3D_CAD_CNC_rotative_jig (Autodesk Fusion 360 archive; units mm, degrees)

design "CNC jig F1-Version02" references "f1_blank", "CNC table work"
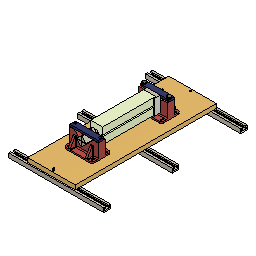
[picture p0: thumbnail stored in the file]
description: Part Number
part number: 94180A353_Brass Tapered Heat-Set Inserts for Plastic
part number: 94459A180_Heat-Set Inserts for Plastic
part number: 96016A241_Plastic-Head Thumb Screws
part number: 92005A218_Steel Pan Head Phillips Screw
part number: 92770A117_Black-Oxide Steel Machined Neck T-Slot Bolt
component_insert "Component Insert1"
position "Position1"
sketch "Sketch2" plane through (0, 0, 0) normal (0, 0, 1) x axis (-1, 0, 0)
  line L1 (0, -35.5) -> (6, -35.5)
  line L2 (0, -65) -> (0, -35.5)
  line L3 (50, -65) -> (0, -65)
  line L4 (50, 0) -> (50, -65)
  line L5 (0, 0) -> (50, 0)
  line L6 (0, -29.5) -> (0, 0)
  line L7 (6, -29.5) -> (0, -29.5)
  line L8 (6, -35.5) -> (6, -29.5)
  line L9 (0, 0) -> (50, -65)
  line L10 (50, 0) -> (0, -65)
  line L11 (25, -53.7132) -> (3.7868, -32.5)
  line L12 (46.2132, -32.5) -> (25, -53.7132)
  line L13 (25, -11.2868) -> (46.2132, -32.5)
  line L14 (3.7868, -32.5) -> (25, -11.2868)
  line L15 (46.2132, -32.5) -> (3.7868, -32.5)
  line L16 (25, -11.2868) -> (25, -53.7132)
  line L17 (25, -4.2157) -> (53.2843, -32.5)
  line L18 (-3.2843, -32.5) -> (25, -4.2157)
  line L19 (25, -60.7843) -> (-3.2843, -32.5)
  line L20 (53.2843, -32.5) -> (25, -60.7843)
  circle C1 centre (29, -32.5) radius 9
  circle C2 centre (29, -32.5) radius 10.5
  point P11 (25, -32.5)
  point P16 (25, -32.5)
  point P14 (46.2132, -32.5)
  point P15 (25, -11.2868)
  point P13 (25, -53.7132)
  midpoint L9 P11
  perpendicular L11 L12
  parallel L11 L13
  parallel L12 L14
  coincident L15 P16
  coincident L16 P16
  coincident P11 P16
  vertical L16
  concentric C1 C2
  dimension "d31" distance P14 P15 = 30
  dimension "d32" distance P13 P14 = 30
  dimension "d36" diameter C2 = 21
  dimension "d42" = 5
sketch "Sketch3" plane through (0, 0, -223) normal (0, 0, -1) x axis (1, 0, 0)
  line L1 (-6, -35.5) -> (0, -35.5)
  line L2 (-6, -29.5) -> (-6, -35.5)
  line L3 (0, -29.5) -> (-6, -29.5)
  line L4 (0, 0) -> (0, -29.5)
  line L5 (-50, 0) -> (0, 0)
  line L6 (-50, -65) -> (-50, 0)
  line L7 (0, -65) -> (-50, -65)
  line L8 (0, -35.5) -> (0, -65)
  line L9 (-50, -32.5) -> (0, -32.5)
  line L10 (-29, 0) -> (-29, -65)
  line L11 (5, 0) -> (-50, 0)
  line L12 (5, -65) -> (5, 0)
  line L13 (-50, -65) -> (5, -65)
  line L14 (-50, 0) -> (-50, -65)
  line L15 (-50, 0) -> (0, -65)
  line L16 (0, 0) -> (-50, -65)
  line L17 (-3.7868, -32.5) -> (-25, -53.7132)
  line L18 (-25, -11.2868) -> (-3.7868, -32.5)
  line L19 (-46.2132, -32.5) -> (-25, -11.2868)
  line L20 (-25, -53.7132) -> (-46.2132, -32.5)
  line L21 (-25, -11.2868) -> (-25, -53.7132)
  line L22 (-46.2132, -32.5) -> (-3.7868, -32.5)
  line L23 (0, -29.5) -> (0, -35.5)
  line L24 (-50, -65) -> (0, -65)
  circle C1 centre (-29, -32.5) radius 9
  point P13 (-50, -32.5)
  point P14 (-29, -65)
  point P15 (-29, 0)
  point P10 (-29, -32.5)
  point P19 (-29, -32.5)
  point P1 (0, 0)
  point P20 (0, 0)
  point P21 (-25, -32.5)
  point P26 (-25, -32.5)
  point P11 (-28.998, -32.6276)
  point P24 (-25, -11.2868)
  point P25 (-46.2132, -32.5)
  point P23 (-3.7868, -32.5)
  midpoint L6 P13
  perpendicular L6 L9
  coincident L7 P14
  coincident L5 P15
  perpendicular L5 L10
  horizontal L11
  vertical L12
  horizontal L13
  vertical L14
  coincident P10 P19
  coincident P1 P20
  midpoint L9 P21
  perpendicular L17 L18
  parallel L17 L19
  parallel L18 L20
  coincident L21 P26
  coincident L22 P26
  coincident P21 P26
  horizontal L22
  dimension "d5" distance L8 L12 = 5
  dimension "d8" distance P11 P21 = 4
  dimension "d9" distance P24 P25 = 30
  dimension "d10" distance P23 P24 = 30
extrude "Extrude1" new body sketch "Sketch3" profile of L1 L2 L3 L4 L8 L11 L13 L14 L17 L18 L19 L20 L23 along normal blind 15 bodies "front end block"
extrude "Extrude2" new body sketch "Sketch3" profile of L4 L8 L11 L12 L13 L23 along normal blind 15 bodies "front end block plate wirh slot"
extrude "Extrude3" new body sketch "Sketch3" profile of L1 L2 L3 L4 L8 L11 L12 L13 L23 against normal blind 10
extrude "Extrude4" sketch "Sketch3" profile of L17 L18 L19 L20 blind 50 bodies "front end square axis"
sketch "Sketch4" plane through (0, 0, -238) normal (0, 0, -1) x axis (-1, 0, 0)
  line L1 (0, 0) -> (0, 65)
  line L2 (50, 0) -> (0, 0)
  line L3 (50, 65) -> (50, 0)
  line L4 (0, 65) -> (50, 65)
  line L5 (46.2132, 32.5) -> (25, 11.2868)
  line L6 (25, 53.7132) -> (46.2132, 32.5)
  line L7 (3.7868, 32.5) -> (25, 53.7132)
  line L8 (25, 11.2868) -> (3.7868, 32.5)
  line L9 (25, -13.7132) -> (25, 11.2868)
  line L10 (85, -13.7132) -> (25, -13.7132)
  line L11 (65, 51.2868) -> (25, 11.2868)
  line L12 (85, 51.2868) -> (65, 51.2868)
  line L13 (85, -13.7132) -> (85, 51.2868)
  line L14 (-5, 0) -> (50, 0)
  line L15 (25, 71.245) -> (25, 11.2868)
  line L16 (25, 51.2868) -> (65, 51.2868)
  line L17 (-35, -13.7132) -> (-35, 51.2868)
  line L18 (-35, 51.2868) -> (-15, 51.2868)
  line L19 (-15, 51.2868) -> (25, 11.2868)
  line L20 (-35, -13.7132) -> (25, -13.7132)
  line L21 (26.5, 11.1475) -> (26.5, 12.7868)
  line L22 (25, 9.6475) -> (25, 9.6475)
  line L23 (23.5, 11.1475) -> (23.5, 12.7868)
  arc A1 centre (25, 11.1475) radius 1.5 clockwise from (26.5, 11.1475) to (25, 9.6475)
  arc A2 centre (25, 11.1475) radius 1.5 clockwise from (25, 9.6475) to (23.5, 11.1475)
  point P6 (25, 11.2868)
  point P10 (25, 11.2868)
  point P17 (25, 11.2868)
  point P19 (25, 51.2868)
  point P23 (25, 11.2868)
  point P11 (25, -13.7132)
  point P24 (25, -13.7132)
  point P12 (65, 51.2868)
  point P22 (-15, 51.2868)
  point P13 (85, 51.2868)
  point P20 (-35, 51.2868)
  point P14 (85, -13.7132)
  point P21 (-35, -13.7132)
  point P25 (26.5, 12.7868)
  point P26 (25, 9.6475)
  point P29 (23.5, 12.7868)
  point P32 (25, 9.6475)
  point P27 (26.5, 11.1475)
  point P30 (23.5, 11.1475)
  coincident P6 P10
  perpendicular L2 L9
  perpendicular L9 L10
  perpendicular L6 L11
  parallel L10 L12
  perpendicular L10 L13
  coincident P6 P17
  perpendicular L4 L15
  coincident L15 P19
  perpendicular L15 L16
  symmetric P10 L9 P23
  symmetric P11 L9 P24
  symmetric L9 P12 P22
  symmetric L9 P13 P20
  symmetric L9 P14 P21
  coincident L11 P25
  vertical L21
  coincident L9 P26
  tangent L21 A1
  symmetric L9 P25 P29
  symmetric L9 P26 P32
  symmetric L9 P27 P30
  symmetric L9 A1 A2
  dimension "d20" distance P10 P11 = 25
  dimension "d26" distance P11 P14 = 60
  dimension "d27" distance P13 P14 = 65
  dimension "d28" angle L11 L14 = 45
  dimension "d62" distance L9 L21 = 1.5
  dimension "d64" radius A1 = 1.5
extrude "Extrude5" new body sketch "Sketch4" profile of L1 L2 L3 L5 L8 L10 L11 L12 L13 L14 L17 L18 L19 L20 L21 A1 L23 A2 along normal blind 30
extrude "Extrude6" new body sketch "Sketch2" profile of C1 against normal blind 50 bodies "rear end axis"
chamfer "Chamfer1" distance 3
extrude "Extrude7" add sketch "Sketch2" profile of C1 L12 L13 C2 along normal blind 30
extrude "Extrude8" sketch "Sketch2" profile of C1 L11 L12 L13 L14 C2 blind 39
hole "Hole1" HoleDepth 12 HoleDiameter 6 TipAngle 118 RefDim1 15 RefDim2 8
hole "Hole2" HoleDepth 12 HoleDiameter 6 TipAngle 118 RefDim1 8 RefDim2 15
copy_paste_bodies "CopyPasteBodies1"
move "Move1"
move "Move2"
extrude "Extrude9" sketch "Sketch2" profile of C1 L11 L12 L13 L14 C2 L17 L18 L19 L20 blind 9
ground "Ground1"
ground "Ground2"
move "Move3"
move "Move4"
sketch "Sketch5" plane through (0, 51.2868, 0) normal (0, 1, 0) x axis (0, 0, -1)
  line L1 (238, -35) -> (238, -15)
  line L2 (268, -35) -> (238, -35)
  line L3 (268, -15) -> (268, -35)
  line L4 (238, -15) -> (268, -15)
  line L5 (238, 65) -> (238, 85)
  line L6 (268, 65) -> (238, 65)
  line L7 (268, 85) -> (268, 65)
  line L8 (238, 85) -> (268, 85)
  line L9 (253, -27) -> (253, 77)
  line L10 (245.5, 85) -> (260.5, 85)
  line L11 (245.5, -35) -> (245.5, 85)
  line L12 (260.5, -35) -> (245.5, -35)
  line L13 (260.5, 85) -> (260.5, -35)
  line L14 (245.5, -35) -> (260.5, 85)
  line L15 (245.5, 73.75) -> (253, 73.75)
  line L16 (245.5, 80.25) -> (253, 80.25)
  line L17 (245.5, -23.75) -> (253, -23.75)
  line L18 (245.5, -30.25) -> (253, -30.25)
  circle C1 centre (253, -27) radius 3
  circle C2 centre (253, 77) radius 3
  circle C3 centre (253, 77) radius 3.25
  circle C4 centre (253, -27) radius 3.25
  point P7 (253, 77)
  point P14 (253, 77)
  point P2 (253, -27)
  point P15 (253, -27)
  point P20 (253, 73.75)
  point P21 (245.5, 73.75)
  point P22 (253, 80.25)
  point P23 (245.5, 80.25)
  point P24 (253, -23.75)
  point P25 (245.5, -23.75)
  point P26 (253, -30.25)
  point P27 (245.5, -30.25)
  point P16 (260.5, 85)
  point P19 (260.5, -35)
  point P17 (245.5, 85)
  concentric C2 C3
  concentric C1 C4
  coincident P7 P14
  coincident P2 P15
  horizontal L10
  vertical L11
  horizontal L12
  vertical L13
  midpoint L9 L14
  coincident C3 P20
  coincident L9 P20
  coincident L11 P21
  tangent C3 L15
  coincident C3 P22
  coincident L11 P23
  tangent C3 L16
  perpendicular L11 L16
  coincident L9 P24
  coincident C4 P24
  coincident L11 P25
  tangent C4 L17
  coincident C4 P26
  coincident L11 P27
  tangent C4 L18
  perpendicular L11 L18
  dimension "d56" diameter C3 = 6.5
  dimension "d57" diameter C4 = 6.5
  dimension "d58" distance P16 P19 = 120
  dimension "d59" distance P16 P17 = 15
extrude "Extrude10" new body sketch "Sketch5" profile of L2 L8 C3 C4 L10 L11 L12 L13 L15 L16 L17 L18 along normal blind 4 bodies "locking plate 1"
combine "Combine1"
component_insert "Component Insert2"
position "Position2"
position "Position3"
sketch "Sketch6" plane through (0, 0, 59) normal (0, 0, 1) x axis (1, 0, 0)
  line L1 (-23.5, 12.7868) -> (15, 51.2868)
  line L2 (-23.5, 11.1475) -> (-23.5, 12.7868)
  line L3 (-26.5, 12.7868) -> (-26.5, 11.1475)
  line L4 (-65, 51.2868) -> (-26.5, 12.7868)
  line L5 (-85, 51.2868) -> (-65, 51.2868)
  line L6 (-85, -13.7132) -> (-85, 51.2868)
  line L7 (35, -13.7132) -> (-85, -13.7132)
  line L8 (35, 51.2868) -> (35, -13.7132)
  line L9 (15, 51.2868) -> (35, 51.2868)
  line L10 (35, -13.7132) -> (35, 16.2868)
  line L11 (55, -13.7132) -> (35, -13.7132)
  line L12 (55, -11.7132) -> (55, -13.7132)
  line L13 (37, 16.2868) -> (35, 16.2868)
  line L14 (37, -11.7132) -> (37, 16.2868)
  line L15 (55, -11.7132) -> (37, -11.7132)
  arc A1 centre (-25, 11.1475) radius 1.5 clockwise from (-23.5, 11.1475) to (-26.5, 11.1475)
  point P13 (35, 16.2868)
  point P14 (35, -13.7132)
  point P15 (55, -13.7132)
  point P16 (55, -11.7132)
  point P17 (37, 16.2868)
  parallel L8 L10
  perpendicular L8 L11
  vertical L12
  perpendicular L10 L13
  perpendicular L13 L14
  perpendicular L12 L15
  dimension "d66" distance P13 P14 = 30
  dimension "d67" distance P14 P15 = 20
  dimension "d68" distance P15 P16 = 2
  dimension "d69" distance P13 P17 = 2
hole "Hole3" HoleDepth 2 HoleDiameter 3 TipAngle 118 RefDim1 7 RefDim2 10 CSDiameter 5 CSAngle 100
work_plane "WorkPlane1"
mirror "Mirror1"
mirror_component "MirrorComponent1"
sketch "Sketch7" plane through (0, 0, 69) normal (0, 0, 1) x axis (1, 0, 0)
  line L1 (-25, 11.2868) -> (-46.2132, 32.5)
  line L2 (-3.7868, 32.5) -> (-25, 11.2868)
  line L3 (-25, 53.7132) -> (-3.7868, 32.5)
  line L4 (-46.2132, 32.5) -> (-25, 53.7132)
  circle C1 centre (-25, 32.5) radius 10
  dimension "d102" diameter C1 = 20
extrude "Extrude11" add sketch "Sketch7" profile of C1 along normal blind 100
chamfer "Chamfer2" distance 2
offset_faces "OffsetFaces1" distance 10
combine "Combine2"
offset_faces "OffsetFaces2" distance -0.15
chamfer "Chamfer3" sketch "Sketch3" distance 2
chamfer "Chamfer4" sketch "Sketch3" distance 2
split "Split1" bodies "handle"
extrude "Extrude12" add of existing geometry blind 4
base_feature "Base Feature1"
move "Move1"
position "Position5"
copy_paste "CopyPaste1"
position "Position6"
position "Position7"
sketch "Sketch8" plane through (0, 0, -268) normal (0, 0, -1) x axis (-1, 0, 0)
  line L1 (-15, 51.2868) -> (23.5, 12.7868)
  line L2 (-35, 51.2868) -> (-15, 51.2868)
  line L3 (-35, -13.7132) -> (-35, 51.2868)
  line L4 (85, -13.7132) -> (-35, -13.7132)
  line L5 (85, 51.2868) -> (85, -13.7132)
  line L6 (65, 51.2868) -> (85, 51.2868)
  line L7 (26.5, 12.7868) -> (65, 51.2868)
  line L8 (26.5, 11.1475) -> (26.5, 12.7868)
  line L9 (23.5, 12.7868) -> (23.5, 11.1475)
  line L10 (30.5, 11.1475) -> (30.5, 12.7868)
  line L11 (19.5, 12.7868) -> (19.5, 11.1475)
  line L12 (85, -7.7132) -> (-35, -7.7132)
  arc A1 centre (25, 11.1475) radius 1.5 clockwise from (26.5, 11.1475) to (23.5, 11.1475)
  point P17 (-35, -7.7132)
  point P18 (85, -7.7132)
  coincident L3 P17
  coincident L5 P18
  perpendicular L5 L12
  dimension "d117" = -4
  dimension "d118" distance L4 L12 = 6
extrude "Extrude13" add sketch "Sketch8" profile of L3 L4 L5 L12 along normal blind 25
sketch "Sketch9" plane through (-85, 0, 0) normal (-1, 0, 0) x axis (0, 0, 1)
  line L1 (-238, 51.2868) -> (-238, -13.7132)
  line L2 (-268, 51.2868) -> (-238, 51.2868)
  line L3 (-268, -7.7132) -> (-268, 51.2868)
  line L4 (-293, -7.7132) -> (-268, -7.7132)
  line L5 (-293, -13.7132) -> (-293, -7.7132)
  line L6 (-238, -13.7132) -> (-293, -13.7132)
  line L7 (-293, -7.7132) -> (-268, -7.7132)
  line L8 (-293, -13.7132) -> (-293, -7.7132)
  line L9 (-293, -13.7132) -> (-238, -13.7132)
  line L10 (-238, -13.7132) -> (-238, 51.2868)
  line L11 (-268, -7.7132) -> (-268, 51.2868)
  line L12 (-268, 51.2868) -> (-238, 51.2868)
  line L13 (-293, -2.7132) -> (-293, -7.7132)
  line L14 (-273, 32.2868) -> (-268, 32.2868)
  line L15 (-293, -2.7132) -> (-273, 32.2868)
  point P9 (-293, -7.7132)
  point P14 (-293, -7.7132)
  point P16 (-268, 32.2868)
  point P15 (-293, -2.7132)
  point P17 (-273, 32.2868)
  coincident P9 P14
  perpendicular L7 L13
  coincident L3 P16
  perpendicular L3 L14
  dimension "d121" distance P14 P15 = 5
  dimension "d122" distance P16 P17 = 5
  dimension "d123" distance L7 L14 = 40
extrude "Extrude14" add sketch "Sketch9" profile of L3 L4 L7 L11 L13 L14 L15 blind -8 from offset -20
work_plane "WorkPlane2"
mirror "Mirror2" mirrorStitchTolerance 0.1
sketch "Sketch10" plane through (0, -7.7132, 0) normal (0, 1, 0) x axis (-1, 0, 0)
  line L1 (-15, -268) -> (-15, -293)
  line L2 (-35, -268) -> (-15, -268)
  line L3 (-35, -293) -> (-35, -268)
  line L4 (-15, -293) -> (-35, -293)
  line L5 (-7, -293) -> (-7, -268)
  line L6 (57, -293) -> (-7, -293)
  line L7 (57, -268) -> (57, -293)
  line L8 (-7, -268) -> (57, -268)
  line L9 (65, -293) -> (65, -268)
  line L10 (85, -293) -> (65, -293)
  line L11 (85, -268) -> (85, -293)
  line L12 (65, -268) -> (85, -268)
  line L13 (-15, -280.5) -> (-35, -280.5)
  line L14 (-25, -293) -> (-25, -268)
  line L15 (-27.6, -283.5) -> (-27.6, -277.5)
  line L16 (-22.4, -277.5) -> (-22.4, -283.5)
  line L17 (-25, -283.5) -> (-25, -277.5)
  line L18 (75, -293) -> (75, -268)
  line L19 (85, -280.5) -> (65, -280.5)
  line L20 (72.4, -283.5) -> (72.4, -277.5)
  line L21 (77.6, -277.5) -> (77.6, -283.5)
  line L22 (75, -283.5) -> (75, -277.5)
  arc A1 centre (-25, -283.5) radius 2.6 clockwise from (-22.4, -283.5) to (-27.6, -283.5)
  arc A2 centre (-25, -277.5) radius 2.6 clockwise from (-27.6, -277.5) to (-22.4, -277.5)
  arc A3 centre (75, -283.5) radius 2.6 clockwise from (77.6, -283.5) to (72.4, -283.5)
  arc A4 centre (75, -277.5) radius 2.6 clockwise from (72.4, -277.5) to (77.6, -277.5)
  point P14 (-35, -280.5)
  point P15 (-15, -280.5)
  point P16 (-25, -268)
  point P17 (-25, -293)
  point P24 (-25, -280.5)
  point P25 (75, -268)
  point P26 (75, -293)
  point P27 (65, -280.5)
  point P28 (85, -280.5)
  point P35 (75, -280.5)
  point P34 (75, -283.5)
  midpoint L3 P14
  midpoint L1 P15
  midpoint L2 P16
  midpoint L4 P17
  tangent L15 A1
  tangent A1 L16
  parallel L15 L16
  tangent L16 A2
  tangent L15 A2
  perpendicular L14 L17
  midpoint L13 P24
  midpoint L17 P24
  midpoint L12 P25
  midpoint L10 P26
  midpoint L9 P27
  midpoint L11 P28
  tangent L20 A3
  tangent A3 L21
  parallel L20 L21
  tangent L21 A4
  tangent L20 A4
  perpendicular L19 L22
  midpoint L19 P35
  midpoint L22 P35
  dimension "d130" diameter A1 = 5.2
  dimension "d131" diameter A3 = 5.2
  dimension "d132" distance L19 P34 = 3
extrude "Extrude15" cut sketch "Sketch10" profile of L15 A1 L16 A2 L20 A3 L21 A4 against normal blind 15
fillet "Fillet1" radius 10
fillet "Fillet2" radius 4
fillet "Fillet3" radius 2
work_plane "WorkPlane3"
mirror "Mirror3" mirrorStitchTolerance 0.1
mirror "Mirror4" mirrorStitchTolerance 0.1
fillet "Fillet4" radius 4
fillet "Fillet5" radius 10
offset_faces "OffsetFaces4" distance 6
combine "Combine3" bodies "front end block plate wirh slot"
combine "Combine4" bodies "front end square axis"
hole "Hole4" HoleDepth 10 HoleDiameter 5 TipAngle 118 RefDim1 15 RefDim2 8
hole "Hole5" HoleDepth 10 HoleDiameter 5 TipAngle 118 RefDim1 15 RefDim2 8
copy_paste "CopyPaste3"
position "Position11"
copy_paste "CopyPaste4"
offset_faces "OffsetFaces5" distance 2
sketch "Sketch11" plane through (0, 0, 39) normal (0, 0, 1) x axis (1, 0, 0)
  line L1 (-25, 60.7843) -> (3.2843, 32.5)
  line L2 (-53.2843, 32.5) -> (-25, 60.7843)
  line L3 (-25, 4.2157) -> (-53.2843, 32.5)
  line L4 (3.2843, 32.5) -> (-25, 4.2157)
  line L5 (-23.5858, 52.299) -> (-26.4142, 52.299)
  line L6 (-5.201, 33.9142) -> (-23.5858, 52.299)
  line L7 (-5.201, 31.0858) -> (-5.201, 33.9142)
  line L8 (-23.5858, 12.701) -> (-5.201, 31.0858)
  line L9 (-26.4142, 12.701) -> (-23.5858, 12.701)
  line L10 (-44.799, 31.0858) -> (-26.4142, 12.701)
  line L11 (-44.799, 33.9142) -> (-44.799, 31.0858)
  line L12 (-26.4142, 52.299) -> (-44.799, 33.9142)
  line L13 (0, 35.5) -> (-6, 35.5)
  line L14 (-6, 35.5) -> (-6, 29.5)
  line L15 (-6, 29.5) -> (0, 29.5)
  line L16 (-3, 35.5) -> (0.2843, 35.5)
  line L17 (-3, 29.5) -> (-3, 35.5)
  line L18 (0.2843, 29.5) -> (-3, 29.5)
  point P20 (0.2843, 35.5)
  point P21 (-3, 35.5)
  point P22 (-3, 29.5)
  point P23 (0.2843, 29.5)
  coincident L1 P20
  midpoint L13 P21
  parallel L13 L16
  midpoint L15 P22
  coincident L4 P23
  perpendicular L17 L18
extrude "Extrude16" cut sketch "Sketch11" profile of L1 L4 L13 L15 L16 L17 L18 against normal blind 15
mirror "Mirror5" mirrorStitchTolerance 0.1 bodies "rear end V-block support", "locking plate 2"
offset_faces "OffsetFaces6" distance 10
extrude "Extrude17" cut of existing geometry blind -10
base_feature "Base Feature1"
move "Move1"
position "Position12"
copy_paste "CopyPaste5"
base_feature "Base Feature1"
position "Position13"
copy_paste "CopyPaste6"
sketch "Sketch12" plane through (0, 65, 0) normal (0, 1, 0) x axis (-1, 0, 0)
  line L1 (0, -223) -> (50, -223)
  line L2 (0, -213) -> (0, -223)
  line L3 (-5, -213) -> (0, -213)
  line L4 (-5, -238) -> (-5, -213)
  line L5 (50, -238) -> (-5, -238)
  line L6 (50, -223) -> (50, -238)
  line L7 (55, -238) -> (50, -238)
  line L8 (55, -213) -> (55, -238)
  line L9 (50, -213) -> (55, -213)
  line L10 (50, -216) -> (50, -238)
  line L11 (47, -213) -> (50, -213)
  line L12 (50, -216) -> (47, -213)
  point P7 (50, -238)
  point P8 (50, -238)
  point P12 (50, -238)
  point P9 (55, -238)
  point P10 (55, -213)
  point P11 (50, -213)
  point P13 (50, -216)
  point P14 (47, -213)
  coincident P7 P8
  perpendicular L6 L7
  perpendicular L3 L8
  perpendicular L8 L9
  coincident P7 P12
  perpendicular L5 L10
  parallel L9 L11
  dimension "d168" distance P8 P9 = 5
  dimension "d169" distance P10 P11 = 5
  dimension "d170" distance P12 P13 = 22
  dimension "d171" distance P11 P14 = 3
extrude "Extrude18" new body sketch "Sketch12" profile of L6 L7 L8 L9 L10 L11 L12 blind -45 from offset -10 bodies "Block locking plate"
hole "Hole6" HoleDepth 10 HoleDiameter 4.5 TipAngle 118 RefDim1 5 RefDim2 8
hole "Hole7" HoleDepth 10 HoleDiameter 4.5 TipAngle 118 RefDim1 8 RefDim2 5
base_feature "Base Feature1"
move "Move1"
position "Position14"
copy_paste "CopyPaste7"
offset_faces "OffsetFaces7" distance -1.5
hole "Hole8" HoleDepth 6 HoleDiameter 2.5 TipAngle 180
hole "Hole9" HoleDepth 6 HoleDiameter 2.5 TipAngle 180
sketch "Sketch13" plane through (0, 0, 79) normal (0, 0, 1) x axis (1, 0, 0)
  line L1 (-23.5858, 12.701) -> (-26.4142, 12.701)
  line L2 (-5.201, 31.0858) -> (-23.5858, 12.701)
  line L3 (-5.201, 33.9142) -> (-5.201, 31.0858)
  line L4 (-23.5858, 52.299) -> (-5.201, 33.9142)
  line L5 (-26.4142, 52.299) -> (-23.5858, 52.299)
  line L6 (-44.799, 33.9142) -> (-26.4142, 52.299)
  line L7 (-44.799, 31.0858) -> (-44.799, 33.9142)
  line L8 (-26.4142, 12.701) -> (-44.799, 31.0858)
  line L9 (-5.201, 32.5) -> (-44.799, 32.5)
  line L10 (-25, 12.701) -> (-25, 52.299)
  circle C1 centre (-25, 32.5) radius 1.25
  point P11 (-44.799, 32.5)
  point P12 (-5.201, 32.5)
  point P13 (-25, 52.299)
  point P14 (-25, 12.701)
  midpoint L7 P11
  midpoint L3 P12
  midpoint L5 P13
  midpoint L1 P14
pipe "Pipe1" SectionSize 1 SectionThickness 0.25
pipe "Pipe2" SectionSize 1 SectionThickness 0.25
sketch "Sketch14" plane through (0, 0, -278) normal (0, 0, -1) x axis (-1, 0, 0)
  line L1 (26.4142, 12.701) -> (23.5858, 12.701)
  line L2 (44.799, 31.0858) -> (26.4142, 12.701)
  line L3 (44.799, 33.9142) -> (44.799, 31.0858)
  line L4 (26.4142, 52.299) -> (44.799, 33.9142)
  line L5 (23.5858, 52.299) -> (26.4142, 52.299)
  line L6 (5.201, 33.9142) -> (23.5858, 52.299)
  line L7 (5.201, 31.0858) -> (5.201, 33.9142)
  line L8 (23.5858, 12.701) -> (5.201, 31.0858)
  line L9 (25, 12.701) -> (25, 52.299)
  line L10 (44.799, 32.5) -> (5.201, 32.5)
  circle C1 centre (25, 32.5) radius 1.25
  point P11 (25, 52.299)
  point P12 (25, 12.701)
  point P13 (5.201, 32.5)
  point P14 (44.799, 32.5)
  midpoint L5 P11
  midpoint L1 P12
  midpoint L7 P13
  midpoint L3 P14
pipe "Pipe3" SectionSize 1 SectionThickness 0.25
pipe "Pipe4" SectionSize 1 SectionThickness 0.25
split "Split2" bodies "rear end axis"
offset_faces "OffsetFaces8" distance -15
move "Move6"
combine "Combine5" bodies "rear end axis"
sketch "Sketch15" plane through (0, -13.7132, 0) normal (0, -1, 0) x axis (1, 0, 0)
  line L1 (-75, -213) -> (25, -213)
  line L2 (-85, -283) -> (-85, -223)
  line L3 (25, -293) -> (-75, -293)
  line L4 (35, -223) -> (35, -283)
  line L5 (27.6, -228.5) -> (27.6, -222.5)
  line L6 (22.4, -222.5) -> (22.4, -228.5)
  line L7 (-72.4, -228.5) -> (-72.4, -222.5)
  line L8 (-77.6, -222.5) -> (-77.6, -228.5)
  line L9 (27.6, -283.5) -> (27.6, -277.5)
  line L10 (22.4, -277.5) -> (22.4, -283.5)
  line L11 (-72.4, -283.5) -> (-72.4, -277.5)
  line L12 (-77.6, -277.5) -> (-77.6, -283.5)
  line L13 (35, 69) -> (35, 9)
  line L14 (-75, 79) -> (25, 79)
  line L15 (-85, 9) -> (-85, 69)
  line L16 (25, -1) -> (-75, -1)
  line L17 (27.6, 8.5) -> (27.6, 14.5)
  line L18 (22.4, 14.5) -> (22.4, 8.5)
  line L19 (-72.4, 8.5) -> (-72.4, 14.5)
  line L20 (-77.6, 14.5) -> (-77.6, 8.5)
  line L21 (27.6, 63.5) -> (27.6, 69.5)
  line L22 (22.4, 69.5) -> (22.4, 63.5)
  line L23 (-72.4, 63.5) -> (-72.4, 69.5)
  line L24 (-77.6, 69.5) -> (-77.6, 63.5)
  line L25 (-25, -293) -> (-25, 79)
  line L26 (-125, -357) -> (75, -357)
  line L27 (-125, 143) -> (-125, -357)
  line L28 (75, 143) -> (-125, 143)
  line L29 (75, -357) -> (75, 143)
  line L30 (-125, -357) -> (75, 143)
  arc A1 centre (25, -223) radius 10 clockwise from (25, -213) to (35, -223)
  arc A2 centre (-75, -223) radius 10 clockwise from (-85, -223) to (-75, -213)
  arc A3 centre (-75, -283) radius 10 clockwise from (-75, -293) to (-85, -283)
  arc A4 centre (25, -283) radius 10 clockwise from (35, -283) to (25, -293)
  arc A5 centre (25, -228.5) radius 2.6 clockwise from (27.6, -228.5) to (22.4, -228.5)
  arc A6 centre (25, -222.5) radius 2.6 clockwise from (22.4, -222.5) to (27.6, -222.5)
  arc A7 centre (-75, -228.5) radius 2.6 clockwise from (-72.4, -228.5) to (-77.6, -228.5)
  arc A8 centre (-75, -222.5) radius 2.6 clockwise from (-77.6, -222.5) to (-72.4, -222.5)
  arc A9 centre (25, -283.5) radius 2.6 clockwise from (27.6, -283.5) to (22.4, -283.5)
  arc A10 centre (25, -277.5) radius 2.6 clockwise from (22.4, -277.5) to (27.6, -277.5)
  arc A11 centre (-75, -283.5) radius 2.6 clockwise from (-72.4, -283.5) to (-77.6, -283.5)
  arc A12 centre (-75, -277.5) radius 2.6 clockwise from (-77.6, -277.5) to (-72.4, -277.5)
  arc A13 centre (25, 9) radius 10 clockwise from (35, 9) to (25, -1)
  arc A14 centre (25, 69) radius 10 clockwise from (25, 79) to (35, 69)
  arc A15 centre (-75, 69) radius 10 clockwise from (-85, 69) to (-75, 79)
  arc A16 centre (-75, 9) radius 10 clockwise from (-75, -1) to (-85, 9)
  arc A17 centre (25, 8.5) radius 2.6 clockwise from (27.6, 8.5) to (22.4, 8.5)
  arc A18 centre (25, 14.5) radius 2.6 clockwise from (22.4, 14.5) to (27.6, 14.5)
  arc A19 centre (-75, 8.5) radius 2.6 clockwise from (-72.4, 8.5) to (-77.6, 8.5)
  arc A20 centre (-75, 14.5) radius 2.6 clockwise from (-77.6, 14.5) to (-72.4, 14.5)
  arc A21 centre (25, 63.5) radius 2.6 clockwise from (27.6, 63.5) to (22.4, 63.5)
  arc A22 centre (25, 69.5) radius 2.6 clockwise from (22.4, 69.5) to (27.6, 69.5)
  arc A23 centre (-75, 63.5) radius 2.6 clockwise from (-72.4, 63.5) to (-77.6, 63.5)
  arc A24 centre (-75, 69.5) radius 2.6 clockwise from (-77.6, 69.5) to (-72.4, 69.5)
  point P74 (-25, 79)
  point P79 (-25, -293)
  point P12 (35, -283)
  point P75 (75, -357)
  point P76 (-125, -357)
  point P78 (75, 143)
  midpoint L14 P74
  perpendicular L14 L25
  horizontal L26
  vertical L27
  horizontal L28
  vertical L29
  coincident L3 P79
  midpoint L25 L30
  dimension "d59" distance P12 = 15
  dimension "d213" distance P75 P76 = 200
  dimension "d214" distance P75 P78 = 500
extrude "Extrude19" new body sketch "Sketch15" profile of A1 L1 A2 L2 A3 L3 A4 L4 A13 L13 A14 L14 A15 L15 A16 L16 L26 L27 L28 L29 along normal blind 18 bodies "MDF Board"
sketch "Sketch16" plane through (0, 0, 0) normal (1, 0, 0) x axis (0, 1, 0)
  line L1 (-31.7132, 143) -> (-31.7132, -357)
  line L2 (-31.7132, -93) -> (-49.7132, -93)
  line L3 (-31.7132, -121) -> (-31.7132, -93)
  line L4 (-49.7132, -121) -> (-31.7132, -121)
  line L5 (-49.7132, -93) -> (-49.7132, -121)
  line L6 (-49.7132, -107) -> (-31.7132, -107)
  line L7 (-36.7132, -97) -> (-43.7132, -97)
  line L8 (-36.7132, -117) -> (-36.7132, -97)
  line L9 (-43.7132, -117) -> (-36.7132, -117)
  line L10 (-43.7132, -97) -> (-43.7132, -117)
  line L11 (-36.7132, -101.5) -> (-31.7132, -101.5)
  line L12 (-31.7132, -112.5) -> (-36.7132, -112.5)
  point P8 (-31.7132, -107)
  point P9 (-49.7132, -107)
  point P14 (-31.7132, -101.5)
  point P15 (-36.7132, -101.5)
  point P16 (-36.7132, -112.5)
  point P17 (-31.7132, -112.5)
  point P4 (-49.7132, -93)
  point P5 (-31.7132, -93)
  point P7 (-49.7132, -121)
  point P10 (-43.7132, -97)
  point P11 (-36.7132, -97)
  point P13 (-43.7132, -117)
  horizontal L2
  vertical L3
  horizontal L4
  vertical L5
  midpoint L3 P8
  midpoint L5 P9
  horizontal L7
  vertical L8
  horizontal L9
  vertical L10
  coincident L3 P14
  coincident L8 P15
  perpendicular L8 L11
  coincident L8 P16
  coincident L3 P17
  perpendicular L3 L12
  collinear L1 L3
  midpoint L1 P8
  dimension "d218" distance P4 P5 = 18
  dimension "d219" distance P4 P7 = 28
  dimension "d220" distance P10 P11 = 7
  dimension "d221" distance P10 P13 = 20
  dimension "d222" distance L3 L8 = 5
  dimension "d223" distance L6 L7 = 10
  dimension "d224" distance L6 L11 = 5.5
  dimension "d225" distance L6 L12 = 5.5
extrude "Extrude20" new body sketch "Sketch16" profile of L2 L3 L4 L5 L7 L8 L9 L10 L11 L12 distance 200
copy_paste_bodies "CopyPasteBodies3"
copy_paste_bodies "CopyPasteBodies4"
move "Move8"
copy_paste_bodies "CopyPasteBodies5"
move "Move9"
offset_faces "OffsetFaces9" distance 47
offset_faces "OffsetFaces10" distance 47
remove_instance "RemoveInstance1"
component_from_bodies "Body->Comp1"
component_from_bodies "Body->Comp2"
component_from_bodies "Body->Comp3"
component_from_bodies "Body->Comp4"
component_from_bodies "Body->Comp5"
component_from_bodies "Body->Comp6"
component_from_bodies "Body->Comp7"
component_from_bodies "Body->Comp8"
component_from_bodies "Body->Comp9"
component_from_bodies "Body->Comp10"
copy_paste "CutPaste1"
copy_paste "CutPaste2"
copy_paste "CutPaste3"
copy_paste "CutPaste1"
copy_paste "CutPaste2"
copy_paste "CutPaste3"
copy_paste "CutPaste4"
copy_paste "CutPaste5"
copy_paste "CutPaste6"
copy_paste "CutPaste7"
copy_paste "CutPaste8"
copy_paste "CutPaste9"
copy_paste "CutPaste10"
component_from_bodies "Body->Comp11"
base_feature "Base Feature1"
position "Position15"
hole "Hole1" HoleDepth 30 HoleDiameter 8 TipAngle 118 RefDim1 9 RefDim2 100
position "Position16"
work_plane "WorkPlane4"
mirror "Mirror1" mirrorStitchTolerance 0.1
sketch "Sketch17" plane through (0, -13.7132, 0) normal (0, 1, 0) x axis (-1, 0, 0)
  line L1 (-75, 190) -> (125, 190)
  line L2 (-75, -404) -> (-75, 190)
  line L3 (125, -404) -> (-75, -404)
  line L4 (125, 190) -> (125, -404)
  line L5 (75, -1) -> (-25, -1)
  line L6 (85, 69) -> (85, 9)
  line L7 (-22.4, 8.5) -> (-22.4, 14.5)
  line L8 (-27.6, 14.5) -> (-27.6, 8.5)
  line L9 (77.6, 8.5) -> (77.6, 14.5)
  line L10 (72.4, 14.5) -> (72.4, 8.5)
  line L11 (75, 79) -> (-25, 79)
  line L12 (-35, 69) -> (-35, 9)
  line L13 (-22.4, 63.5) -> (-22.4, 69.5)
  line L14 (-27.6, 69.5) -> (-27.6, 63.5)
  line L15 (77.6, 63.5) -> (77.6, 69.5)
  line L16 (72.4, 69.5) -> (72.4, 63.5)
  line L17 (75, -213) -> (-25, -213)
  line L18 (85, -283) -> (85, -223)
  line L19 (-22.4, -222.5) -> (-22.4, -228.5)
  line L20 (-27.6, -228.5) -> (-27.6, -222.5)
  line L21 (77.6, -222.5) -> (77.6, -228.5)
  line L22 (72.4, -228.5) -> (72.4, -222.5)
  line L23 (75, -293) -> (-25, -293)
  line L24 (-35, -283) -> (-35, -223)
  line L25 (-22.4, -277.5) -> (-22.4, -283.5)
  line L26 (-27.6, -283.5) -> (-27.6, -277.5)
  line L27 (77.6, -277.5) -> (77.6, -283.5)
  line L28 (72.4, -283.5) -> (72.4, -277.5)
  line L29 (25, -404) -> (25, 190)
  line L30 (85, 79) -> (-35, 79)
  line L31 (85, -293) -> (85, 79)
  line L32 (-35, -293) -> (85, -293)
  line L33 (-35, 79) -> (-35, -293)
  circle C1 centre (25, -395) radius 4
  circle C2 centre (25, 181) radius 4
  arc A1 centre (-25, 9) radius 10 clockwise from (-25, -1) to (-35, 9)
  arc A2 centre (75, 9) radius 10 clockwise from (85, 9) to (75, -1)
  arc A3 centre (-25, 8.5) radius 2.6 clockwise from (-22.4, 8.5) to (-27.6, 8.5)
  arc A4 centre (-25, 14.5) radius 2.6 clockwise from (-27.6, 14.5) to (-22.4, 14.5)
  arc A5 centre (75, 8.5) radius 2.6 clockwise from (77.6, 8.5) to (72.4, 8.5)
  arc A6 centre (75, 14.5) radius 2.6 clockwise from (72.4, 14.5) to (77.6, 14.5)
  arc A7 centre (75, 69) radius 10 clockwise from (75, 79) to (85, 69)
  arc A8 centre (-25, 69) radius 10 clockwise from (-35, 69) to (-25, 79)
  arc A9 centre (-25, 63.5) radius 2.6 clockwise from (-22.4, 63.5) to (-27.6, 63.5)
  arc A10 centre (-25, 69.5) radius 2.6 clockwise from (-27.6, 69.5) to (-22.4, 69.5)
  arc A11 centre (75, 63.5) radius 2.6 clockwise from (77.6, 63.5) to (72.4, 63.5)
  arc A12 centre (75, 69.5) radius 2.6 clockwise from (72.4, 69.5) to (77.6, 69.5)
  arc A13 centre (-25, -223) radius 10 clockwise from (-35, -223) to (-25, -213)
  arc A14 centre (75, -223) radius 10 clockwise from (75, -213) to (85, -223)
  arc A15 centre (-25, -222.5) radius 2.6 clockwise from (-27.6, -222.5) to (-22.4, -222.5)
  arc A16 centre (-25, -228.5) radius 2.6 clockwise from (-22.4, -228.5) to (-27.6, -228.5)
  arc A17 centre (75, -222.5) radius 2.6 clockwise from (72.4, -222.5) to (77.6, -222.5)
  arc A18 centre (75, -228.5) radius 2.6 clockwise from (77.6, -228.5) to (72.4, -228.5)
  arc A19 centre (75, -283) radius 10 clockwise from (85, -283) to (75, -293)
  arc A20 centre (-25, -283) radius 10 clockwise from (-25, -293) to (-35, -283)
  arc A21 centre (-25, -277.5) radius 2.6 clockwise from (-27.6, -277.5) to (-22.4, -277.5)
  arc A22 centre (-25, -283.5) radius 2.6 clockwise from (-22.4, -283.5) to (-27.6, -283.5)
  arc A23 centre (75, -277.5) radius 2.6 clockwise from (72.4, -277.5) to (77.6, -277.5)
  arc A24 centre (75, -283.5) radius 2.6 clockwise from (77.6, -283.5) to (72.4, -283.5)
  point P80 (25, 190)
  point P81 (25, -404)
  midpoint L1 P80
  midpoint L3 P81
  horizontal L30
  vertical L31
  horizontal L32
  vertical L33
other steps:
base_feature "Base Feature1" bodies "MDF Board"
base_feature "Base Feature1" bodies "locking plate 1"
base_feature "Base Feature1" bodies "front end block"
base_feature "Base Feature1" bodies "front end V-block support"
base_feature "Base Feature1" bodies "rear end V-block support"
base_feature "Base Feature1" bodies "locking plate 2"
base_feature "Base Feature1" bodies "rear end axis"
base_feature "Base Feature1" bodies "T slot rail (2)"
base_feature "Base Feature1" bodies "T slot rail (1)"
base_feature "Base Feature1" bodies "T slot rail"
mirror "Mirror1" mirrorStitchTolerance 0.1
base_feature "Base Feature1" bodies "Block locking plate"
base_feature "Base Feature1" bodies "rear end V-Block"
base_feature "Base Feature3" bodies "T slot rail (2)"
base_feature "Base Feature4" bodies "T slot rail (1)"
base_feature "Base Feature5" bodies "T slot rail"
create_component "CreateComponent3"
create_component "CreateComponent5"
create_component "CreateComponent6"
hole "Hole1" HoleDepth 10 HoleDiameter 4.5 TipAngle 118 RefDim1 8 RefDim2 5
create_component "CreateComponent7"
create_component "CreateComponent8"
remove_body "RemoveBody1"
create_component "CreateComponent9"
remove_body "RemoveBody2"
create_component "CreateComponent10"
remove_body "RemoveBody3"
create_component "CreateComponent11"
remove_body "RemoveBody4"
create_component "CreateComponent12"
remove_body "RemoveBody5"
create_component "CreateComponent13"
remove_body "RemoveBody6"
create_component "CreateComponent14"
remove_body "RemoveBody7"
create_component "CreateComponent15"
remove_body "RemoveBody8"
create_component "CreateComponent16"
remove_body "RemoveBody9"
create_component "CreateComponent17"
remove_body "RemoveBody10"
create_component "CreateComponent18"
remove_instance "RemoveInstance2"
remove_instance "RemoveInstance3"
remove_instance "RemoveInstance4"
create_component "CreateComponent19"
remove_instance "RemoveInstance5"
remove_instance "RemoveInstance6"
remove_instance "RemoveInstance7"
remove_instance "RemoveInstance8"
remove_instance "RemoveInstance9"
remove_instance "RemoveInstance10"
remove_instance "RemoveInstance11"
remove_instance "RemoveInstance12"
remove_instance "RemoveInstance13"
remove_instance "RemoveInstance14"
create_component "CreateComponent20"
remove_body "RemoveBody11"
create_component "CreateComponent22"
hole "Hole1" HoleDepth 30 HoleDiameter 8 TipAngle 118 RefDim1 9 RefDim2 100
named bodies: "front end block", "front end block plate wirh slot", "front end square axis", "front end V-block support", "rear end axis", "rear end V-Block", "locking plate 1", "handle", "rear end V-block support", "locking plate 2", "Block locking plate", "MDF Board", "T slot rail (2)", "T slot rail (1)", "T slot rail"

design "CNC table work"
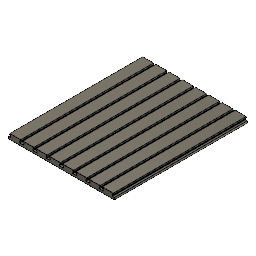
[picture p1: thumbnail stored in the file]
sketch "Sketch1" plane through (0, 0, 0) normal (0, 0, 1) x axis (1, 0, 0)
  line L1 (397.6, 0) -> (0, 0)
  line L2 (0, 20) -> (0, 0)
  line L3 (45.65, 20) -> (4.05, 20)
  line L4 (4.05, 15.1) -> (4.05, 20)
  line L5 (7.285, 15.1) -> (4.05, 15.1)
  line L6 (7.285, 8.2) -> (7.285, 15.1)
  line L7 (0, 8.2) -> (7.285, 8.2)
  line L8 (0, 20) -> (0, 8.2)
  line L9 (24.85, 8.2) -> (24.85, 20)
  line L10 (49.7, 20) -> (49.7, 8.2)
  line L11 (45.65, 15.1) -> (45.65, 20)
  line L12 (42.415, 15.1) -> (45.65, 15.1)
  line L13 (42.415, 8.2) -> (42.415, 15.1)
  line L14 (49.7, 8.2) -> (42.415, 8.2)
  line L15 (95.35, 20) -> (53.75, 20)
  line L16 (53.75, 15.1) -> (53.75, 20)
  line L17 (56.985, 15.1) -> (53.75, 15.1)
  line L18 (56.985, 8.2) -> (56.985, 15.1)
  line L19 (49.7, 8.2) -> (56.985, 8.2)
  line L20 (95.35, 15.1) -> (95.35, 20)
  line L21 (92.115, 15.1) -> (95.35, 15.1)
  line L22 (92.115, 8.2) -> (92.115, 15.1)
  line L23 (99.4, 8.2) -> (92.115, 8.2)
  line L24 (145.05, 20) -> (103.45, 20)
  line L25 (103.45, 15.1) -> (103.45, 20)
  line L26 (106.685, 15.1) -> (103.45, 15.1)
  line L27 (106.685, 8.2) -> (106.685, 15.1)
  line L28 (99.4, 8.2) -> (106.685, 8.2)
  line L29 (145.05, 15.1) -> (145.05, 20)
  line L30 (141.815, 8.2) -> (141.815, 15.1)
  line L31 (149.1, 8.2) -> (141.815, 8.2)
  line L32 (141.815, 15.1) -> (145.05, 15.1)
  line L33 (194.75, 20) -> (153.15, 20)
  line L34 (153.15, 15.1) -> (153.15, 20)
  line L35 (156.385, 15.1) -> (153.15, 15.1)
  line L36 (156.385, 8.2) -> (156.385, 15.1)
  line L37 (149.1, 8.2) -> (156.385, 8.2)
  line L38 (191.515, 15.1) -> (194.75, 15.1)
  line L39 (191.515, 8.2) -> (191.515, 15.1)
  line L40 (198.8, 8.2) -> (191.515, 8.2)
  line L41 (194.75, 15.1) -> (194.75, 20)
  line L42 (244.45, 20) -> (202.85, 20)
  line L43 (202.85, 15.1) -> (202.85, 20)
  line L44 (206.085, 15.1) -> (202.85, 15.1)
  line L45 (206.085, 8.2) -> (206.085, 15.1)
  line L46 (198.8, 8.2) -> (206.085, 8.2)
  line L47 (241.215, 15.1) -> (244.45, 15.1)
  line L48 (241.215, 8.2) -> (241.215, 15.1)
  line L49 (248.5, 8.2) -> (241.215, 8.2)
  line L50 (244.45, 15.1) -> (244.45, 20)
  line L51 (294.15, 20) -> (252.55, 20)
  line L52 (252.55, 15.1) -> (252.55, 20)
  line L53 (255.785, 15.1) -> (252.55, 15.1)
  line L54 (255.785, 8.2) -> (255.785, 15.1)
  line L55 (248.5, 8.2) -> (255.785, 8.2)
  line L56 (294.15, 15.1) -> (294.15, 20)
  line L57 (290.915, 8.2) -> (290.915, 15.1)
  line L58 (298.2, 8.2) -> (290.915, 8.2)
  line L59 (290.915, 15.1) -> (294.15, 15.1)
  line L60 (343.85, 20) -> (302.25, 20)
  line L61 (305.485, 15.1) -> (302.25, 15.1)
  line L62 (305.485, 8.2) -> (305.485, 15.1)
  line L63 (298.2, 8.2) -> (305.485, 8.2)
  line L64 (302.25, 15.1) -> (302.25, 20)
  line L65 (343.85, 15.1) -> (343.85, 20)
  line L66 (340.615, 15.1) -> (343.85, 15.1)
  line L67 (347.9, 8.2) -> (340.615, 8.2)
  line L68 (340.615, 8.2) -> (340.615, 15.1)
  line L69 (393.55, 20) -> (351.95, 20)
  line L70 (351.95, 15.1) -> (351.95, 20)
  line L71 (355.185, 15.1) -> (351.95, 15.1)
  line L72 (355.185, 8.2) -> (355.185, 15.1)
  line L73 (347.9, 8.2) -> (355.185, 8.2)
  line L74 (393.55, 15.1) -> (393.55, 20)
  line L75 (390.315, 15.1) -> (393.55, 15.1)
  line L76 (397.6, 8.2) -> (390.315, 8.2)
  line L77 (390.315, 8.2) -> (390.315, 15.1)
  line L78 (397.6, 0) -> (397.6, 8.2)
  point P1 (0, 0)
  point P2 (0, 0)
  point P3 (0, 0)
  point P12 (24.85, 20)
  point P5 (4.05, 20)
  point P16 (45.65, 20)
  point P7 (4.05, 15.1)
  point P17 (45.65, 15.1)
  point P8 (7.285, 15.1)
  point P18 (42.415, 15.1)
  point P9 (7.285, 8.2)
  point P19 (42.415, 8.2)
  point P10 (0, 8.2)
  point P14 (49.7, 8.2)
  point P11 (0, 20)
  point P15 (49.7, 20)
  point P4 (0, 20)
  point P6 (45.65, 20)
  point P27 (53.75, 20)
  point P28 (95.35, 20)
  point P21 (53.75, 15.1)
  point P20 (56.985, 8.2)
  point P29 (56.985, 15.1)
  point P49 (103.45, 20)
  point P50 (145.05, 20)
  point P40 (103.45, 15.1)
  point P37 (106.685, 8.2)
  point P51 (106.685, 15.1)
  point P31 (153.15, 20)
  point P38 (194.75, 20)
  point P43 (153.15, 15.1)
  point P39 (156.385, 15.1)
  point P42 (156.385, 8.2)
  point P93 (202.85, 20)
  point P94 (244.45, 20)
  point P62 (202.85, 15.1)
  point P59 (206.085, 8.2)
  point P95 (206.085, 15.1)
  point P53 (252.55, 20)
  point P60 (294.15, 20)
  point P65 (252.55, 15.1)
  point P61 (255.785, 15.1)
  point P64 (255.785, 8.2)
  point P75 (302.25, 20)
  point P91 (343.85, 20)
  point P69 (302.25, 15.1)
  point P82 (305.485, 8.2)
  point P92 (305.485, 15.1)
  point P80 (351.95, 20)
  point P86 (393.55, 20)
  point P70 (351.95, 15.1)
  point P83 (355.185, 8.2)
  point P89 (355.185, 15.1)
  coincident P1 P2
  horizontal L1
  coincident P1 P3
  perpendicular L1 L2
  horizontal L3
  perpendicular L3 L4
  perpendicular L4 L5
  perpendicular L5 L6
  perpendicular L6 L7
  perpendicular L3 L8
  midpoint L3 P12
  perpendicular L7 L9
  symmetric P5 L9 P16
  symmetric P7 L9 P17
  symmetric P8 L9 P18
  symmetric P9 L9 P19
  symmetric P10 L9 P14
  symmetric P11 L9 P15
  horizontal L15
  perpendicular L15 L16
  perpendicular L16 L17
  perpendicular L17 L18
  perpendicular L18 L19
  horizontal L24
  perpendicular L24 L25
  perpendicular L25 L26
  perpendicular L26 L27
  perpendicular L27 L28
  horizontal L33
  perpendicular L33 L34
  perpendicular L34 L35
  perpendicular L35 L36
  perpendicular L36 L37
  horizontal L42
  perpendicular L42 L43
  perpendicular L43 L44
  perpendicular L44 L45
  perpendicular L45 L46
  horizontal L51
  perpendicular L51 L52
  perpendicular L52 L53
  perpendicular L53 L54
  perpendicular L54 L55
  horizontal L60
  perpendicular L60 L64
  perpendicular L61 L64
  perpendicular L61 L62
  perpendicular L62 L63
  horizontal L69
  perpendicular L69 L70
  perpendicular L70 L71
  perpendicular L71 L72
  perpendicular L72 L73
  perpendicular L1 L78
  dimension "d2" distance P3 P4 = 20
  dimension "d3" distance P5 P6 = 41.6
  dimension "d4" distance P5 P7 = 4.9
  dimension "d5" distance P8 P9 = 6.9
  dimension "d7" distance L4 L8 = 4.05
  dimension "d8" distance P9 P10 = 7.285
  dimension "d9" distance P27 P28 = 41.6
  dimension "d10" distance P21 P27 = 4.9
  dimension "d11" distance P20 P29 = 6.9
  dimension "d12" distance P49 P50 = 41.6
  dimension "d13" distance P40 P49 = 4.9
  dimension "d14" distance P37 P51 = 6.9
  dimension "d15" distance P31 P38 = 41.6
  dimension "d16" distance P31 P43 = 4.9
  dimension "d17" distance P39 P42 = 6.9
  dimension "d18" distance P93 P94 = 41.6
  dimension "d19" distance P62 P93 = 4.9
  dimension "d20" distance P59 P95 = 6.9
  dimension "d21" distance P53 P60 = 41.6
  dimension "d22" distance P53 P65 = 4.9
  dimension "d23" distance P61 P64 = 6.9
  dimension "d24" distance P75 P91 = 41.6
  dimension "d25" distance P69 P75 = 4.9
  dimension "d26" distance P82 P92 = 6.9
  dimension "d27" distance P80 P86 = 41.6
  dimension "d28" distance P70 P80 = 4.9
  dimension "d29" distance P83 P89 = 6.9
extrude "Extrude1" new body sketch "Sketch1" profile of L1 L2 L3 L4 L5 L6 L7 L11 L12 L13 L14 L15 L16 L17 L18 L19 L20 L21 L22 L23 L24 L25 L26 L27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 along normal blind 500

design "f1_blank"
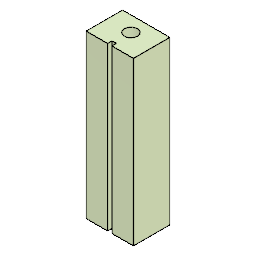
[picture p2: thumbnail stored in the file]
